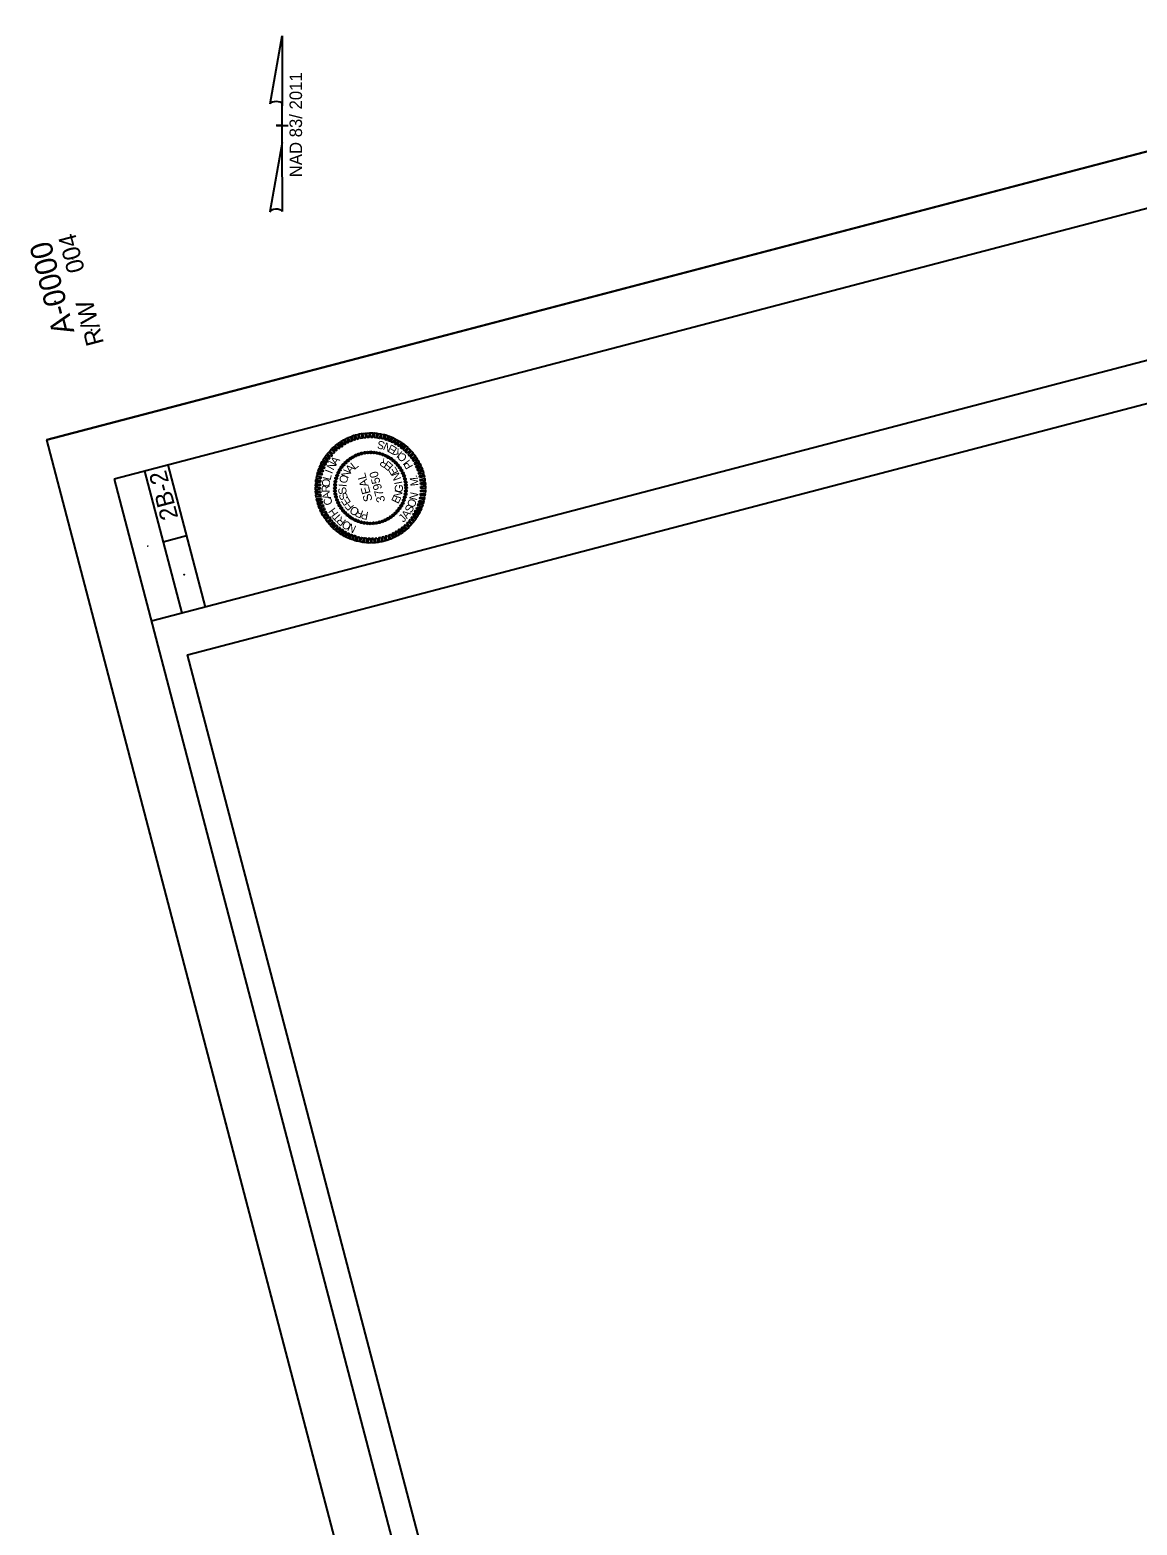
# Model space of a CAD drawing. Extents: x 1366396 to 1367943, y 879298 to 881235.
# Drawn here: x 1366396 to 1367149, y 880204 to 881221 of the extents above; entities that cross this region are included whole.
import ezdxf

# ---------------------------------------------------------------- set-up
doc = ezdxf.new("R2010")
doc.units = 0
for name, color, linetype in [('Draft_RDY_Construction_Class_Element', 7, 'Continuous'), ('Old_Level_1', 7, 'Continuous'), ('Old_Level_2', 7, 'Continuous'), ('Prop CMT Slope Fill', 7, 'Continuous'), ('Prop Conc 2ft 6in Curb and Gutter', 7, 'Continuous'), ('Prop GRAU CAT1 Cell', 7, 'Continuous'), ('Prop Superelevation Label', 7, 'Continuous'), ('Scratch_Level_6', 7, 'Continuous')]:
    doc.layers.add(name, color=color, linetype=linetype)

msp = doc.modelspace()

# ---------------------------------------------------------------- linework, layer by layer
at = {"layer": 'Draft_RDY_Construction_Class_Element'}
msp.add_lwpolyline([(1366838.5, 879297.8), (1366407.5, 880942.3), (1367471.6, 881221.1), (1367902.6, 879576.7)], close=True, dxfattribs=at)
at = {"layer": 'Old_Level_1'}
for p in [(1367471.6, 881221.1), (1366838.5, 879297.8)]:
    msp.add_line(p, (1366407.5, 880942.3), dxfattribs=at)
for centre in [(1366488.4, 880898.9), (1366476.3, 880869.9), (1366501, 880850.5)]:
    msp.add_circle(centre, 0.06, dxfattribs=at)
at = {"layer": 'Old_Level_2'}
for centre in [(1366425.3, 881065.4), (1366413.2, 881036.4), (1366437.9, 881017)]:
    msp.add_circle(centre, 0.06, dxfattribs=at)
at = {"layer": 'Prop CMT Slope Fill'}
for p, q in [((1366610.7, 880926.7), (1366610.7, 880926.7)), ((1366612.3, 880928.2), (1366612.3, 880928.2)), ((1366613.9, 880929.4), (1366613.9, 880929.4)), ((1366615.7, 880930.6), (1366615.7, 880930.6)), ((1366617.7, 880931.5), (1366617.7, 880931.5)), ((1366619.6, 880932.3), (1366619.6, 880932.3)), ((1366621.6, 880933), (1366621.6, 880933)), ((1366623.7, 880933.4), (1366623.7, 880933.4)), ((1366625.8, 880933.6), (1366625.8, 880933.6)), ((1366627.9, 880933.8), (1366627.9, 880933.8)), ((1366630, 880933.7), (1366630, 880933.7)), ((1366632.1, 880933.3), (1366632.1, 880933.3)), ((1366634.2, 880932.9), (1366634.2, 880932.9)), ((1366636.2, 880932.2), (1366636.2, 880932.2)), ((1366638.2, 880931.4), (1366638.2, 880931.4)), ((1366640, 880930.4), (1366640, 880930.4)), ((1366641.8, 880929.3), (1366641.8, 880929.3)), ((1366643.4, 880928), (1366643.4, 880928)), ((1366645, 880926.5), (1366645, 880926.5)), ((1366604.4, 880915.9), (1366604.4, 880915.9)), ((1366605.1, 880917.9), (1366605.1, 880917.9)), ((1366605.8, 880919.9), (1366605.8, 880919.9)), ((1366606.8, 880921.7), (1366606.8, 880921.7)), ((1366608, 880923.6), (1366608, 880923.6)), ((1366609.3, 880925.2), (1366609.3, 880925.2)), ((1366646.4, 880925), (1366646.4, 880925)), ((1366647.7, 880923.3), (1366647.7, 880923.3)), ((1366648.8, 880921.5), (1366648.8, 880921.5)), ((1366649.8, 880919.6), (1366649.8, 880919.6)), ((1366650.6, 880917.7), (1366650.6, 880917.7)), ((1366603.5, 880909.6), (1366603.5, 880909.6)), ((1366603.6, 880911.8), (1366603.6, 880911.8)), ((1366603.6, 880907.5), (1366603.6, 880907.5)), ((1366603.9, 880913.8), (1366603.9, 880913.8)), ((1366627.8, 880909.5), (1366627.8, 880909.5)), ((1366651.2, 880915.6), (1366651.2, 880915.6)), ((1366651.7, 880913.6), (1366651.7, 880913.6)), ((1366651.9, 880911.5), (1366651.9, 880911.5)), ((1366651.9, 880907.3), (1366651.9, 880907.3)), ((1366652, 880909.4), (1366652, 880909.4)), ((1366603.9, 880905.5), (1366603.9, 880905.5)), ((1366604.3, 880903.4), (1366604.3, 880903.4)), ((1366604.9, 880901.3), (1366604.9, 880901.3)), ((1366605.8, 880899.4), (1366605.8, 880899.4)), ((1366606.7, 880897.5), (1366606.7, 880897.5)), ((1366607.8, 880895.7), (1366607.8, 880895.7)), ((1366648.7, 880897.3), (1366648.7, 880897.3)), ((1366649.7, 880899.1), (1366649.7, 880899.1)), ((1366650.5, 880901.1), (1366650.5, 880901.1)), ((1366651.2, 880903.1), (1366651.2, 880903.1)), ((1366651.6, 880905.2), (1366651.6, 880905.2)), ((1366609.1, 880894), (1366609.1, 880894)), ((1366610.5, 880892.5), (1366610.5, 880892.5)), ((1366612.1, 880891), (1366612.1, 880891)), ((1366613.7, 880889.7), (1366613.7, 880889.7)), ((1366615.5, 880888.6), (1366615.5, 880888.6)), ((1366617.4, 880887.6), (1366617.4, 880887.6)), ((1366619.4, 880886.8), (1366619.4, 880886.8)), ((1366621.4, 880886.1), (1366621.4, 880886.1)), ((1366623.4, 880885.7), (1366623.4, 880885.7)), ((1366625.5, 880885.4), (1366625.5, 880885.4)), ((1366629.7, 880885.4), (1366629.7, 880885.4)), ((1366631.8, 880885.6), (1366631.8, 880885.6)), ((1366633.9, 880886.1), (1366633.9, 880886.1)), ((1366635.9, 880886.7), (1366635.9, 880886.7)), ((1366637.9, 880887.5), (1366637.9, 880887.5)), ((1366639.8, 880888.5), (1366639.8, 880888.5)), ((1366641.6, 880889.6), (1366641.6, 880889.6)), ((1366643.3, 880890.8), (1366643.3, 880890.8)), ((1366644.8, 880892.3), (1366644.8, 880892.3)), ((1366646.3, 880893.8), (1366646.3, 880893.8)), ((1366647.6, 880895.5), (1366647.6, 880895.5)), ((1366627.7, 880885.2), (1366627.7, 880885.2))]:
    msp.add_line(p, q, dxfattribs=at)
for points in [[(1366620.8, 880943.1), (1366620.1, 880946.2), (1366621.7, 880946.5), (1366622, 880943.3)], [(1366623.1, 880943.5), (1366622.6, 880946.6), (1366624.2, 880946.8), (1366624.3, 880943.6)], [(1366625.6, 880943.8), (1366625.2, 880946.8), (1366626.8, 880946.9), (1366626.7, 880943.7)], [(1366628, 880943.8), (1366627.8, 880946.9), (1366629.4, 880947), (1366629.1, 880943.7)], [(1366630.4, 880943.8), (1366630.5, 880946.9), (1366632.1, 880946.7), (1366631.6, 880943.5)], [(1366632.8, 880943.4), (1366633, 880946.6), (1366634.6, 880946.3), (1366633.9, 880943.2)], [(1366604.1, 880934.4), (1366601.8, 880936.5), (1366603.1, 880937.5), (1366604.9, 880935.2)], [(1366605.9, 880935.9), (1366603.7, 880938.2), (1366605, 880939.2), (1366606.8, 880936.6)], [(1366607.8, 880937.3), (1366605.8, 880939.8), (1366607.1, 880940.7), (1366608.7, 880938)], [(1366609.9, 880938.7), (1366607.9, 880941.4), (1366609.4, 880942.1), (1366610.7, 880939.3)], [(1366611.9, 880939.9), (1366610.2, 880942.5), (1366611.7, 880943.3), (1366612.8, 880940.4)], [(1366614, 880940.9), (1366612.5, 880943.7), (1366614.1, 880944.3), (1366615.1, 880941.4)], [(1366616.2, 880941.8), (1366615, 880944.7), (1366616.5, 880945.3), (1366617.3, 880942.2)], [(1366618.5, 880942.5), (1366617.5, 880945.5), (1366619.1, 880945.9), (1366619.6, 880942.8)], [(1366635.1, 880943.1), (1366635.6, 880946.1), (1366637.2, 880945.8), (1366636.2, 880942.8)], [(1366637.5, 880942.5), (1366638.1, 880945.5), (1366639.7, 880945), (1366638.5, 880942)], [(1366639.7, 880941.6), (1366640.6, 880944.6), (1366642.2, 880944.1), (1366640.8, 880941.3)], [(1366641.9, 880940.7), (1366643, 880943.7), (1366644.5, 880943), (1366642.9, 880940.3)], [(1366644.1, 880939.6), (1366645.3, 880942.5), (1366646.7, 880941.7), (1366645, 880939.1)], [(1366646.2, 880938.5), (1366647.6, 880941.2), (1366649.1, 880940.4), (1366647.1, 880937.8)], [(1366648.1, 880937.1), (1366649.8, 880939.7), (1366651.1, 880938.7), (1366649, 880936.4)], [(1366650, 880935.7), (1366651.9, 880938.1), (1366653.1, 880937.1), (1366650.9, 880934.8)], [(1366651.7, 880934), (1366653.8, 880936.4), (1366654.9, 880935.2), (1366652.6, 880933.3)], [(1366597.1, 880924.7), (1366594.1, 880925.9), (1366594.9, 880927.4), (1366597.5, 880925.8)], [(1366598.2, 880926.8), (1366595.5, 880928.2), (1366596.3, 880929.7), (1366598.8, 880927.7)], [(1366599.4, 880928.9), (1366596.8, 880930.5), (1366597.7, 880931.8), (1366600.2, 880929.8)], [(1366600.9, 880930.8), (1366598.3, 880932.6), (1366599.4, 880933.8), (1366601.6, 880931.6)], [(1366602.4, 880932.6), (1366600, 880934.6), (1366601.1, 880935.8), (1366603.2, 880933.5)], [(1366653.4, 880932.3), (1366655.6, 880934.5), (1366656.7, 880933.3), (1366654.1, 880931.4)], [(1366655, 880930.5), (1366657.3, 880932.5), (1366658.3, 880931.3), (1366655.6, 880929.5)], [(1366656.4, 880928.5), (1366658.8, 880930.3), (1366659.7, 880929), (1366657, 880927.6)], [(1366657.6, 880926.4), (1366660.2, 880928.2), (1366661, 880926.7), (1366658.1, 880925.5)], [(1366594.1, 880915.6), (1366591, 880916), (1366591.2, 880917.7), (1366594.3, 880916.8)], [(1366594.5, 880918.1), (1366591.5, 880918.6), (1366591.9, 880920.2), (1366594.8, 880919.1)], [(1366595.3, 880920.2), (1366592.1, 880921.1), (1366592.8, 880922.6), (1366595.5, 880921.4)], [(1366596.1, 880922.5), (1366593.1, 880923.5), (1366593.8, 880925), (1366596.5, 880923.6)], [(1366658.7, 880924.3), (1366661.5, 880925.9), (1366662.1, 880924.4), (1366659.2, 880923.2)], [(1366659.6, 880922.2), (1366662.5, 880923.5), (1366663.1, 880922), (1366660.1, 880921.1)], [(1366660.5, 880919.9), (1366663.5, 880921), (1366663.9, 880919.4), (1366660.8, 880918.8)], [(1366661.1, 880917.7), (1366664.1, 880918.5), (1366664.5, 880917), (1366661.4, 880916.5)], [(1366661.6, 880915.3), (1366664.7, 880916), (1366664.8, 880914.3), (1366661.7, 880914.1)], [(1366593.5, 880908.6), (1366590.4, 880908.2), (1366590.3, 880909.9), (1366593.5, 880909.6)], [(1366593.5, 880911), (1366590.4, 880910.9), (1366590.5, 880912.4), (1366593.6, 880912)], [(1366593.7, 880906.1), (1366590.6, 880905.6), (1366590.4, 880907.2), (1366593.5, 880907.2)], [(1366593.8, 880913.3), (1366590.5, 880913.5), (1366590.7, 880915), (1366593.8, 880914.5)], [(1366661.8, 880905.7), (1366665, 880905.5), (1366664.8, 880904), (1366661.8, 880904.6)], [(1366661.9, 880913), (1366665, 880913.4), (1366665.2, 880911.8), (1366662, 880911.8)], [(1366662, 880910.4), (1366665.2, 880910.8), (1366665.2, 880909.1), (1366662.1, 880909.4)], [(1366662, 880908), (1366665.1, 880908.2), (1366665.1, 880906.6), (1366662, 880907)], [(1366593.9, 880903.7), (1366590.9, 880903.1), (1366590.7, 880904.7), (1366593.8, 880904.9)], [(1366594.5, 880901.4), (1366591.4, 880900.5), (1366591, 880902.1), (1366594.2, 880902.5)], [(1366595, 880899.1), (1366592.1, 880898), (1366591.7, 880899.6), (1366594.8, 880900.2)], [(1366595.9, 880896.8), (1366593.1, 880895.5), (1366592.5, 880897), (1366595.5, 880897.9)], [(1366596.8, 880894.7), (1366594.1, 880893.1), (1366593.5, 880894.6), (1366596.4, 880895.8)], [(1366659.4, 880896.5), (1366662.5, 880895.5), (1366661.8, 880894), (1366659, 880895.4)], [(1366660.3, 880898.8), (1366663.4, 880897.9), (1366662.8, 880896.4), (1366660, 880897.6)], [(1366661, 880900.9), (1366664, 880900.4), (1366663.6, 880898.8), (1366660.7, 880899.9)], [(1366661.5, 880903.4), (1366664.6, 880903), (1366664.3, 880901.4), (1366661.3, 880902.2)], [(1366598, 880892.6), (1366595.3, 880890.8), (1366594.5, 880892.3), (1366597.5, 880893.5)], [(1366599.2, 880890.5), (1366596.7, 880888.7), (1366595.9, 880890), (1366598.6, 880891.4)], [(1366600.6, 880888.5), (1366598.2, 880886.5), (1366597.3, 880887.7), (1366600, 880889.6)], [(1366602.1, 880886.7), (1366599.9, 880884.5), (1366598.9, 880885.7), (1366601.4, 880887.6)], [(1366603.8, 880885), (1366601.8, 880882.6), (1366600.6, 880883.8), (1366603, 880885.7)], [(1366653.1, 880886.4), (1366655.6, 880884.5), (1366654.4, 880883.2), (1366652.4, 880885.5)], [(1366654.7, 880888.2), (1366657.3, 880886.4), (1366656.2, 880885.2), (1366654, 880887.4)], [(1366656.1, 880890.1), (1366658.8, 880888.5), (1366657.8, 880887.2), (1366655.4, 880889.2)], [(1366657.3, 880892.2), (1366660.1, 880890.8), (1366659.3, 880889.4), (1366656.8, 880891.3)], [(1366658.5, 880894.3), (1366661.4, 880893.1), (1366660.6, 880891.6), (1366658, 880893.2)], [(1366605.5, 880883.3), (1366603.7, 880880.9), (1366602.4, 880881.9), (1366604.7, 880884.2)], [(1366607.4, 880881.9), (1366605.8, 880879.3), (1366604.4, 880880.3), (1366606.6, 880882.6)], [(1366609.4, 880880.5), (1366607.9, 880877.8), (1366606.5, 880878.7), (1366608.5, 880881.2)], [(1366611.5, 880879.4), (1366610.2, 880876.5), (1366608.8, 880877.3), (1366610.5, 880879.9)], [(1366613.7, 880878.3), (1366612.5, 880875.3), (1366611, 880876), (1366612.7, 880878.7)], [(1366615.8, 880877.4), (1366615, 880874.4), (1366613.4, 880874.9), (1366614.8, 880877.7)], [(1366618.1, 880876.5), (1366617.4, 880873.5), (1366615.9, 880874.1), (1366617, 880877)], [(1366620.4, 880875.9), (1366620, 880873), (1366618.3, 880873.3), (1366619.4, 880876.2)], [(1366622.8, 880875.6), (1366622.5, 880872.4), (1366620.9, 880872.7), (1366621.6, 880875.8)], [(1366625.1, 880875.3), (1366625.1, 880872.1), (1366623.5, 880872.3), (1366624, 880875.5)], [(1366627.5, 880875.2), (1366627.7, 880872.1), (1366626.1, 880872), (1366626.5, 880875.3)], [(1366629.9, 880875.2), (1366630.4, 880872.2), (1366628.7, 880872.1), (1366628.9, 880875.3)], [(1366632.4, 880875.5), (1366633, 880872.4), (1366631.3, 880872.2), (1366631.2, 880875.4)], [(1366634.7, 880875.9), (1366635.5, 880872.8), (1366633.9, 880872.5), (1366633.6, 880875.7)], [(1366637, 880876.5), (1366638, 880873.5), (1366636.4, 880873.1), (1366635.9, 880876.2)], [(1366639.4, 880877.2), (1366640.6, 880874.3), (1366639, 880873.7), (1366638.3, 880876.8)], [(1366641.5, 880878.1), (1366643, 880875.3), (1366641.5, 880874.7), (1366640.4, 880877.6)], [(1366643.6, 880879.1), (1366645.3, 880876.5), (1366643.8, 880875.7), (1366642.7, 880878.6)], [(1366645.7, 880880.3), (1366647.6, 880877.7), (1366646.1, 880876.9), (1366644.8, 880879.7)], [(1366647.7, 880881.7), (1366649.7, 880879.2), (1366648.4, 880878.3), (1366646.9, 880881)], [(1366649.7, 880883.2), (1366651.8, 880880.8), (1366650.5, 880879.8), (1366648.8, 880882.4)], [(1366651.4, 880884.6), (1366653.8, 880882.5), (1366652.5, 880881.5), (1366650.7, 880883.8)]]:
    msp.add_lwpolyline(points, close=True, dxfattribs=at)
for centre, major_axis, ratio in [((1366610.7, 880926.7), (-0.487, 0.496), 0.999707), ((1366612.3, 880928.1), (-0.442, 0.537), 0.999707), ((1366614, 880929.4), (-0.394, 0.573), 0.999706), ((1366615.8, 880930.5), (-0.343, 0.605), 0.999706), ((1366617.7, 880931.5), (-0.289, 0.632), 0.999706), ((1366619.6, 880932.3), (-0.234, 0.655), 0.999706), ((1366621.6, 880932.9), (-0.176, 0.673), 0.999706), ((1366623.7, 880933.4), (-0.117, 0.685), 0.999706), ((1366625.8, 880933.6), (-0.058, 0.693), 0.999706), ((1366627.9, 880933.7), (0.002, 0.695), 0.999706), ((1366630, 880933.6), (0.063, 0.693), 0.999706), ((1366632.1, 880933.3), (0.122, 0.684), 0.999707), ((1366634.2, 880932.9), (0.181, 0.671), 0.999707), ((1366636.2, 880932.2), (0.239, 0.653), 0.999707), ((1366638.1, 880931.4), (0.295, 0.63), 0.999708), ((1366640, 880930.4), (0.348, 0.602), 0.999708), ((1366641.8, 880929.3), (0.4, 0.569), 0.999709), ((1366643.4, 880928), (0.448, 0.532), 0.999709), ((1366645, 880926.5), (0.493, 0.491), 0.99971), ((1366604.4, 880915.9), (-0.67, 0.186), 0.99971), ((1366605.1, 880917.9), (-0.651, 0.244), 0.999709), ((1366605.9, 880919.9), (-0.627, 0.3), 0.999709), ((1366606.9, 880921.7), (-0.599, 0.353), 0.999708), ((1366608, 880923.5), (-0.566, 0.404), 0.999708), ((1366609.3, 880925.2), (-0.528, 0.452), 0.999707), ((1366646.4, 880925), (0.534, 0.446), 0.99971), ((1366647.7, 880923.3), (0.571, 0.397), 0.99971), ((1366648.8, 880921.5), (0.603, 0.346), 0.99971), ((1366649.8, 880919.6), (0.631, 0.291), 0.999711), ((1366650.6, 880917.7), (0.655, 0.235), 0.999711), ((1366651.2, 880915.6), (0.673, 0.176), 0.999711), ((1366603.7, 880911.7), (-0.692, 0.066), 0.99971), ((1366603.6, 880909.6), (-0.695, 0.005), 0.99971), ((1366603.6, 880907.5), (-0.693, -0.056), 0.999711), ((1366603.9, 880905.4), (-0.686, -0.116), 0.999711), ((1366603.9, 880913.8), (-0.684, 0.127), 0.99971), ((1366651.7, 880913.6), (0.686, 0.116), 0.999711), ((1366651.6, 880905.2), (0.684, -0.127), 0.99971), ((1366651.9, 880911.5), (0.693, 0.056), 0.999711), ((1366651.9, 880907.3), (0.692, -0.066), 0.99971), ((1366652, 880909.4), (0.695, -0.005), 0.99971), ((1366604.3, 880903.4), (-0.673, -0.176), 0.999711), ((1366605, 880901.3), (-0.655, -0.235), 0.999711), ((1366605.8, 880899.4), (-0.631, -0.291), 0.999711), ((1366606.7, 880897.5), (-0.603, -0.346), 0.99971), ((1366607.9, 880895.7), (-0.571, -0.397), 0.99971), ((1366647.5, 880895.5), (0.566, -0.404), 0.999708), ((1366648.7, 880897.3), (0.599, -0.353), 0.999708), ((1366649.7, 880899.1), (0.627, -0.3), 0.999709), ((1366650.5, 880901.1), (0.651, -0.244), 0.999709), ((1366651.1, 880903.1), (0.67, -0.186), 0.99971), ((1366609.1, 880894), (-0.534, -0.446), 0.99971), ((1366610.6, 880892.5), (-0.493, -0.491), 0.99971), ((1366612.1, 880891), (-0.448, -0.532), 0.999709), ((1366613.8, 880889.7), (-0.4, -0.569), 0.999709), ((1366615.5, 880888.6), (-0.348, -0.602), 0.999708), ((1366617.4, 880887.6), (-0.295, -0.63), 0.999708), ((1366619.4, 880886.8), (-0.239, -0.653), 0.999707), ((1366621.4, 880886.1), (-0.181, -0.671), 0.999707), ((1366623.4, 880885.7), (-0.122, -0.684), 0.999707), ((1366625.5, 880885.4), (-0.063, -0.693), 0.999706), ((1366627.6, 880885.3), (-0.002, -0.695), 0.999706), ((1366629.8, 880885.4), (0.058, -0.693), 0.999706), ((1366631.8, 880885.6), (0.117, -0.685), 0.999706), ((1366633.9, 880886.1), (0.176, -0.673), 0.999706), ((1366635.9, 880886.7), (0.234, -0.655), 0.999706), ((1366637.9, 880887.5), (0.289, -0.632), 0.999706), ((1366639.8, 880888.5), (0.343, -0.605), 0.999706), ((1366641.6, 880889.6), (0.394, -0.573), 0.999706), ((1366643.2, 880890.9), (0.442, -0.537), 0.999707), ((1366644.8, 880892.3), (0.487, -0.496), 0.999707), ((1366646.2, 880893.8), (0.528, -0.452), 0.999707)]:
    msp.add_ellipse(centre, major_axis=major_axis, ratio=ratio, dxfattribs=at)
at = {"layer": 'Prop Conc 2ft 6in Curb and Gutter'}
for p, q in [((1366559.5, 881170.9), (1366567.7, 881217.2)), ((1366567.7, 881217.2), (1366567.7, 881217.2)), ((1366567.7, 881217.2), (1366567.7, 881217.2)), ((1366567.7, 881217.2), (1366567.7, 881169.4)), ((1366567.7, 881144.6), (1366567.7, 881170.8)), ((1366567.7, 881169.4), (1366567.7, 881170.8)), ((1366567.3, 881156.2), (1366563.7, 881156.2)), ((1366563.7, 881156.2), (1366563.7, 881156.2)), ((1366563.8, 881156.2), (1366571.8, 881156.2)), ((1366567.7, 881144.6), (1366559.4, 881097.4)), ((1366567.8, 881097.6), (1366567.7, 881144.6))]:
    msp.add_line(p, q, dxfattribs=at)
for centre, start_param, end_param in [((1366563.6, 881170.4), 0.216388, 2.908219), ((1366563.6, 881097.2), 0.201328, 3.141593)]:
    msp.add_ellipse(centre, major_axis=(4.23, -0.03), ratio=0.461098, start_param=start_param, end_param=end_param, dxfattribs=at)
at = {"layer": 'Prop GRAU CAT1 Cell'}
msp.add_lwpolyline([(1366870, 879396.1), (1366503.2, 880795.9), (1367465.8, 881048.1), (1367814.9, 879716.1)], close=True, dxfattribs=at)
at = {"layer": 'Prop Superelevation Label'}
for p, q in [((1367444.8, 881175.3), (1366453.3, 880915.5)), ((1367470.2, 881078.6), (1366478.7, 880818.8)), ((1366474, 880920.9), (1366499.4, 880824.2)), ((1366490, 880925.1), (1366515.3, 880828.4)), ((1366453.3, 880915.5), (1366865.3, 879343.6)), ((1366502.7, 880876.8), (1366486.7, 880872.6))]:
    msp.add_line(p, q, dxfattribs=at)

# ---------------------------------------------------------------- texts
at = {"layer": 'Old_Level_2'}
for s, height, p in [('004', 12, (1366433.5, 881057.6)), ('A-0000', 15, (1366426.4, 881015.8)), ('R/W', 12, (1366446.5, 881008)), ('2B-2', 12, (1366497.1, 880889.4))]:
    msp.add_text(s, height=height, rotation=104.6851, dxfattribs=at).set_placement(p)
at = {"layer": 'Prop CMT Slope Fill'}
for s, height, rotation, p in [('S', 5.46, 164.7452, (1366638, 880940.6)), ('N', 5.46, 155.468, (1366642.9, 880938.5)), ('E', 5.46, 148.3514, (1366646.4, 880936.4)), ('K', 5.46, 140.5331, (1366649.9, 880933.7)), ('N', 5.45, 61.5041, (1366602.5, 880921.1)), ('A', 5.45, 54.3023, (1366604.5, 880924.6)), ('L', 5.45, 38.086, (1366616.9, 880921.7)), ('R', 5.45, 148.1665, (1366640.6, 880927.2)), ('E', 5.45, 138.8091, (1366643.7, 880924.6)), ('C', 5.46, 131.9391, (1366653.2, 880930.1)), ('I', 5.46, 126.7985, (1366655, 880927.7)), ('P', 5.46, 119.6819, (1366657, 880924.2)), ('L', 5.45, 75.906, (1366600.5, 880914.3)), ('I', 5.45, 68.7053, (1366601.7, 880918.7)), ('O', 5.45, 75.5187, (1366611.5, 880912.1)), ('N', 5.45, 66.1618, (1366612.5, 880915.7)), ('A', 5.45, 47.4454, (1366614.2, 880919)), ('SEAL', 5.79, 104.8532, (1366629.2, 880901)), ('37950', 5.79, 104.6851, (1366637.9, 880900.5)), ('E', 5.45, 120.0968, (1366646.9, 880920.1)), ('N', 5.44, 110.7415, (1366648.8, 880915.7)), ('M', 5.46, 95.6821, (1366660.5, 880911)), ('.', 5.46, 105.4395, (1366659.7, 880916.6)), ('O', 5.44, 83.1063, (1366599.9, 880909.8)), ('R', 5.45, 90.3062, (1366600.1, 880906.4)), ('A', 5.44, 104.7054, (1366601, 880902.5)), ('S', 5.44, 103.5855, (1366611.9, 880905.8)), ('I', 5.45, 84.8748, (1366611.4, 880910)), ('S', 5.44, 112.9407, (1366612.8, 880902.5)), ('N', 5.45, 73.3191, (1366648.3, 880901.8)), ('I', 5.44, 101.3863, (1366649.5, 880912.5)), ('G', 5.45, 82.6754, (1366649.4, 880906)), ('N', 5.46, 77.4417, (1366659.3, 880900.7)), ('C', 5.44, 111.905, (1366602.3, 880898.9)), ('H', 5.45, 126.3045, (1366606.2, 880892.3)), ('E', 5.45, 122.2961, (1366614.7, 880899.6)), ('F', 5.44, 131.6521, (1366616.9, 880897)), ('O', 5.45, 150.3663, (1366620.6, 880894.7)), ('E', 5.45, 63.9621, (1366646.6, 880898.3)), ('S', 5.46, 60.42, (1366655.4, 880891.9)), ('O', 5.46, 67.6659, (1366657.4, 880895.5)), ('T', 5.45, 133.5048, (1366608.5, 880889.8)), ('R', 5.45, 140.7056, (1366611.5, 880887.2)), ('O', 5.45, 147.9068, (1366615.3, 880884.8)), ('N', 5.45, 155.1085, (1366618.6, 880883.4)), ('R', 5.45, 159.7247, (1366623.3, 880893.7)), ('P', 5.45, 169.0839, (1366626.7, 880893)), ('J', 5.46, 46.2588, (1366650.2, 880885.7)), ('A', 5.46, 52.2692, (1366652.6, 880888.1))]:
    msp.add_text(s, height=height, rotation=rotation, dxfattribs=at).set_placement(p)
at = {"layer": 'Scratch_Level_6'}
msp.add_text('NAD 83/ 2011', height=8.5, rotation=90, dxfattribs=at).set_placement((1366581.2, 881120.9))

doc.saveas('drawing.dxf')
